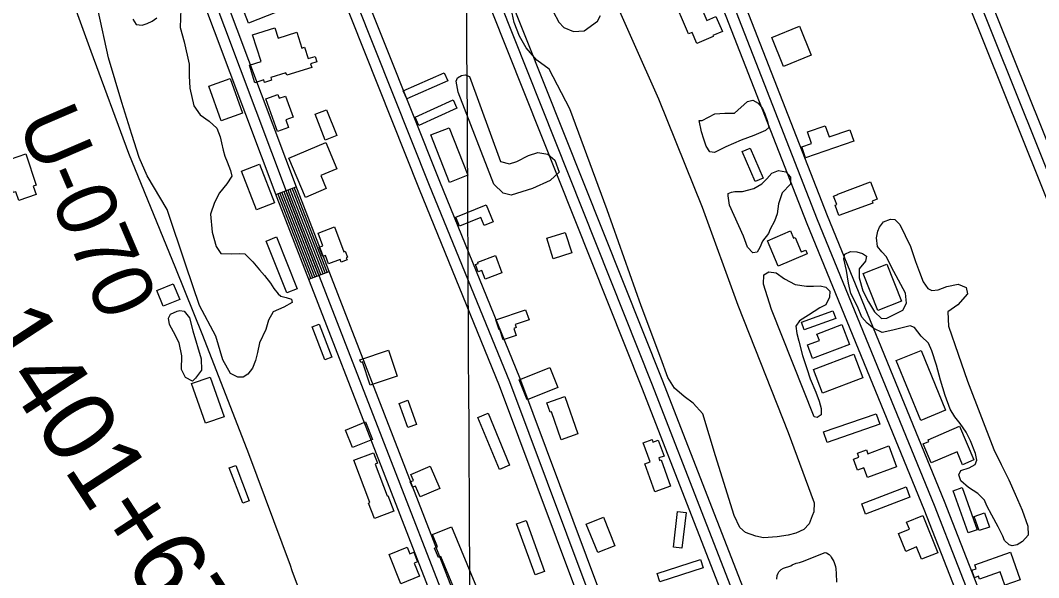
# Model space of a CAD drawing. Extents: x 3445503 to 3483459, y 540493 to 566012.
# Drawn here: x 3475391 to 3476792, y 549267 to 550033 of the extents above; entities that cross this region are included whole.
import ezdxf

# ---------------------------------------------------------------- set-up
doc = ezdxf.new("R2010")
doc.units = 0
for name, color, linetype in [('V-BLDG-OTLN', 7, 'Continuous'), ('V-GRID-MAJR', 7, 'Continuous'), ('V-RIVR-RANG-IDEN', 7, 'Continuous'), ('V-ROAD-CNTR', 7, 'Continuous'), ('V-SITE-VEGE', 7, 'Continuous'), ('V-SURV-IDEN', 7, 'Continuous')]:
    doc.layers.add(name, color=color, linetype=linetype)

msp = doc.modelspace()

# ---------------------------------------------------------------- linework, layer by layer
at = {"layer": 'V-BLDG-OTLN'}
for points in [[(3475743.2, 550044.1), (3475704.4, 550029.3), (3475685.8, 550078), (3475724.6, 550092.8)], [(3476310, 550014.4), (3476287.5, 550067.2), (3476318.5, 550080.4), (3476327.3, 550059.6), (3476324.2, 550058.3), (3476334.9, 550033), (3476347.7, 550038.4), (3476356.5, 550017.9), (3476343.3, 550012.3), (3476344, 550010.7), (3476321.5, 550001.1), (3476314.9, 550016.5)], [(3476462.6, 550024.8), (3476478.8, 549985), (3476440.7, 549969.5), (3476424.5, 550009.3)], [(3475713.4, 549947.3), (3475705.8, 549971.4), (3475721.8, 549976.4), (3475710.2, 550012.9), (3475740.9, 550022.6), (3475745.3, 550008.6), (3475771, 550016.7), (3475777.8, 549995), (3475781.7, 549996.2), (3475786.6, 549980.4), (3475796.5, 549983.5), (3475798.8, 549976), (3475790.1, 549973.3), (3475791.7, 549968.3), (3475757.2, 549957.5), (3475756.1, 549960.9), (3475735.1, 549954.3), (3475736.3, 549950.6), (3475726.6, 549947.5), (3475725.5, 549951.2)], [(3475917.5, 549936.1), (3475973.9, 549960.9), (3475978.8, 549949.7), (3475922.4, 549925)], [(3475666.9, 549894.8), (3475649.9, 549942.4), (3475679.2, 549952.9), (3475696.2, 549905.3)], [(3475744.7, 549880.2), (3475728.5, 549925), (3475745.1, 549931), (3475746.9, 549925.9), (3475755.6, 549929), (3475766.1, 549899.8), (3475755.9, 549896.2), (3475759.7, 549885.6)], [(3475933.7, 549900.1), (3475986, 549923.9), (3475991.3, 549912.2), (3475939.1, 549888.4)], [(3475812.1, 549910.2), (3475826, 549874.6), (3475810.2, 549868.4), (3475796.3, 549904)], [(3475980.7, 549885.3), (3476006.2, 549820.1), (3475981.2, 549810.3), (3475955.6, 549875.4)], [(3476537.3, 549866.9), (3476470.7, 549844.1), (3476465.7, 549858.9), (3476479, 549863.5), (3476473.5, 549879.6), (3476498.1, 549888), (3476503.4, 549872.7), (3476531.9, 549882.4)], [(3475782.9, 549789.6), (3475760, 549843.7), (3475811, 549865.3), (3475826.3, 549829.1), (3475804.1, 549819.6), (3475811.6, 549801.7)], [(3476401.8, 549811.5), (3476383.8, 549852.6), (3476394.7, 549857.3), (3476412.7, 549816.2)], [(3475381, 549796.2), (3475366.7, 549838.7), (3475398.1, 549849.3), (3475412.5, 549806.4), (3475408.4, 549805), (3475412.3, 549793.4), (3475388.6, 549785.4), (3475384.6, 549797.4)], [(3475719.8, 549835.3), (3475740.5, 549782.2), (3475715.8, 549772.6), (3475695.1, 549825.7)], [(3476516.9, 549764.5), (3476511.5, 549778.8), (3476514, 549779.7), (3476509.6, 549791.4), (3476515.3, 549793.5), (3476515.2, 549794), (3476560.4, 549811), (3476569.4, 549787.2), (3476562.4, 549784.5), (3476563.3, 549781.9)], [(3476031.6, 549779.3), (3476041, 549755.8), (3476028.7, 549750.8), (3476024.2, 549762), (3475994.8, 549750.2), (3475989.8, 549762.6)], [(3475800.3, 549740.6), (3475823, 549749.1), (3475835.8, 549715), (3475837.8, 549715.8), (3475841, 549707.5), (3475838.9, 549706.7), (3475840.1, 549703.6), (3475832.1, 549700.5), (3475830.7, 549704.1), (3475814.7, 549698.1), (3475810.4, 549709.6), (3475806.8, 549708.2), (3475801.9, 549721.2), (3475806.9, 549723.1)], [(3475757.3, 549658.4), (3475729, 549729.6), (3475743.2, 549735.2), (3475771.5, 549664)], [(3476123.9, 549705.3), (3476115, 549733.5), (3476140.3, 549741.5), (3476149.2, 549713.3)], [(3476418.5, 549730), (3476450.4, 549743.5), (3476454.5, 549733.7), (3476456.6, 549734.5), (3476465, 549714.6), (3476471.2, 549717.2), (3476473.3, 549712.2), (3476433.2, 549695.2)], [(3476044.2, 549709.7), (3476053.2, 549685.7), (3476030.2, 549677.1), (3476025.8, 549689.1), (3476020.7, 549687.2), (3476016.8, 549697.5), (3476020.5, 549698.9), (3476019.9, 549700.6)], [(3476582.9, 549698), (3476603.1, 549647.1), (3476570.3, 549634.1), (3476550.1, 549684.9)], [(3475601, 549671), (3475609.9, 549649.3), (3475587.3, 549640), (3475578.3, 549661.7)], [(3476044.7, 549621.3), (3476085.8, 549635.2), (3476090.6, 549621.1), (3476071.6, 549614.7), (3476073, 549610.6), (3476069.7, 549609.5), (3476073, 549599.9), (3476055.1, 549593.8), (3476050.4, 549607.8), (3476049.4, 549607.5)], [(3476465.2, 549618), (3476508.6, 549633.6), (3476512.4, 549623.1), (3476468.9, 549607.5)], [(3475809.7, 549566.3), (3475792.3, 549611.5), (3475801.6, 549615.2), (3475819.1, 549569.9)], [(3476486.6, 549601.7), (3476520.8, 549614.7), (3476531.2, 549587.2), (3476480.7, 549568), (3476473.5, 549586.9), (3476489.9, 549593.1)], [(3475857.9, 549566.5), (3475897.2, 549579.4), (3475909, 549543.7), (3475872.1, 549531.6), (3475861.6, 549563.4), (3475859.2, 549562.6)], [(3476629.5, 549483), (3476595.8, 549565.3), (3476629.9, 549579.2), (3476663.5, 549496.9)], [(3476549.5, 549541.6), (3476494.1, 549520.6), (3476481.8, 549553), (3476537.2, 549574.1)], [(3476130.3, 549528.4), (3476087.8, 549511.3), (3476076.8, 549538.6), (3476119.3, 549555.7)], [(3475651.7, 549542.6), (3475670.9, 549488.1), (3475645.6, 549479.2), (3475626.4, 549533.7)], [(3475923.8, 549473.1), (3475911.7, 549506.3), (3475923.8, 549510.7), (3475935.9, 549477.4)], [(3476139.8, 549515.8), (3476157.7, 549464.6), (3476134.6, 549456.5), (3476121.2, 549495), (3476119.4, 549494.4), (3476114.9, 549507.2)], [(3476049.8, 549415.6), (3476020.2, 549487.2), (3476034.1, 549493), (3476063.7, 549421.4)], [(3476495.8, 549467.2), (3476567.9, 549492.2), (3476572.9, 549477.8), (3476500.8, 549452.8)], [(3475875.3, 549457), (3475847.6, 549445.8), (3475837.9, 549469.8), (3475865.6, 549481)], [(3476682.7, 549474.9), (3476702.5, 549428.7), (3476687, 549422), (3476679.3, 549440), (3476643.6, 549424.8), (3476632.6, 549450.6), (3476640.5, 549454), (3476639.4, 549456.4)], [(3476263.5, 549384.9), (3476249.6, 549423.2), (3476257, 549425.9), (3476247.5, 549452.1), (3476259.9, 549456.6), (3476261, 549453.3), (3476268.3, 549455.9), (3476276.2, 549434), (3476268.9, 549431.4), (3476270.1, 549428), (3476272.1, 549428.8), (3476285.1, 549392.7)], [(3475877.8, 549348.1), (3475869.7, 549369.3), (3475871.5, 549370), (3475849.3, 549428.3), (3475876.5, 549438.6), (3475882, 549424.1), (3475878.8, 549422.9), (3475895.4, 549379.3), (3475896.3, 549379.7), (3475904.5, 549358.2)], [(3476596.2, 549419.3), (3476556, 549404.6), (3476551.1, 549417.8), (3476542.5, 549414.7), (3476536.9, 549429.8), (3476544.2, 549432.5), (3476542.2, 549438), (3476554.8, 549442.6), (3476556.8, 549437.2), (3476585.7, 549447.9)], [(3475696.6, 549369.3), (3475678.2, 549417.9), (3475687, 549421.2), (3475705.4, 549372.6)], [(3475954.6, 549420), (3475967.7, 549389.5), (3475940.7, 549378), (3475934.4, 549392.8), (3475930.3, 549391.1), (3475927.2, 549398.4), (3475931.7, 549400.3), (3475928.1, 549408.7)], [(3476548.2, 549368.2), (3476609.2, 549391.5), (3476614.6, 549377.3), (3476553.6, 549354)], [(3476694.6, 549328.5), (3476674, 549386.2), (3476686.2, 549390.6), (3476706.8, 549332.8)], [(3476289.4, 549308.7), (3476294.9, 549357.8), (3476306.5, 549356.5), (3476300.9, 549307.4)], [(3476632.2, 549352.1), (3476652.8, 549301.2), (3476630.5, 549292.1), (3476623.6, 549309), (3476608.9, 549303), (3476599, 549327.4), (3476613.7, 549333.4), (3476609.8, 549343)], [(3476709.8, 549331.5), (3476703.1, 549350.9), (3476717.2, 549355.8), (3476723.9, 549336.4)], [(3476098.9, 549270.6), (3476073.4, 549340.8), (3476086.4, 549345.5), (3476111.9, 549275.3)], [(3476192.9, 549350.1), (3476208.6, 549310.8), (3476185, 549301.3), (3476169.2, 549340.6)], [(3475984, 549336.9), (3476018.1, 549253.6), (3475991.2, 549242.6), (3475969.4, 549295.9), (3475965.8, 549294.4), (3475960.4, 549307.6), (3475964.4, 549309.3), (3475957.5, 549326)], [(3475914.3, 549258.4), (3475898.1, 549298.6), (3475922.9, 549308.6), (3475926.5, 549299.5), (3475931.9, 549301.7), (3475937.1, 549288.7), (3475932.5, 549286.9), (3475939.9, 549268.7)], [(3476752.8, 549301.7), (3476766.3, 549263.8), (3476745.3, 549256.4), (3476738.8, 549274.7), (3476710.4, 549264.7), (3476709, 549268.8), (3476703.2, 549266.8), (3476699.6, 549277.1), (3476705.6, 549279.2), (3476703.8, 549284.4)], [(3476266.9, 549272.5), (3476326.5, 549291.7), (3476330.1, 549280.5), (3476270.5, 549261.3)]]:
    msp.add_lwpolyline(points, close=True, dxfattribs=at)
at = {"layer": 'V-GRID-MAJR'}
msp.add_spline([(3476027.1, 546019.5), (3475994.4, 552078.6), (3475961.8, 558139.5), (3475929.2, 564200.5), (3475929.2, 564202.4)], degree=3, dxfattribs=at)
at = {"layer": 'V-ROAD-CNTR'}
for p, q in [((3475742.2, 549793.7), (3475770.3, 549804.3)), ((3475787.5, 549677), (3475815.5, 549687.9))]:
    msp.add_line(p, q, dxfattribs=at)
for points in [[(3478296.3, 546039.2), (3478195.7, 546296.9), (3478120.9, 546488), (3477825.2, 547231), (3477600.7, 547804.3), (3477368.4, 548418.2), (3477244.1, 548737.9), (3476896.7, 549634.2), (3476496.3, 550631.4), (3476398.8, 550925.5)], [(3477343.6, 548398.8), (3477340.4, 548407.5), (3477216.1, 548727.1), (3476868.8, 549623.2), (3476468.1, 550621), (3476372.9, 550908.5)], [(3476396.2, 550885.7), (3476482.2, 550626.2), (3476882.7, 549628.7), (3477230.1, 548732.5), (3477354.4, 548412.9), (3477586.7, 547798.9), (3477811.3, 547225.5), (3478106.9, 546482.4), (3478181.8, 546291.4), (3478282.2, 546034.2)], [(3476119.7, 550739.7), (3476500.6, 549764.8), (3476661.6, 549372.2), (3476889.8, 548787.9), (3477039.2, 548392.8)], [(3476091.7, 550728.7), (3476472.8, 549753.7), (3476633.8, 549361), (3476861.8, 548777.2), (3477011.1, 548382.2)], [(3476105.7, 550734.2), (3476486.7, 549759.2), (3476647.7, 549366.6), (3476875.8, 548782.5), (3477025.1, 548387.5)], [(3475865.9, 550573.8), (3475950.6, 550349.5), (3476273.1, 549539.7), (3476424.4, 549151), (3476669.7, 548517.3), (3476798.4, 548193.1), (3476918.1, 547887.8)], [(3475837.8, 550563.2), (3475922.6, 550338.7), (3476245.2, 549528.7), (3476396.4, 549140.1), (3476641.7, 548506.4), (3476770.4, 548182.1), (3476890.1, 547876.8)], [(3475851.8, 550568.5), (3475936.6, 550344.1), (3476259.2, 549534.2), (3476410.4, 549145.6), (3476655.7, 548511.8), (3476784.4, 548187.6), (3476904.1, 547882.3)], [(3476433.7, 548569), (3476247.4, 549046), (3476063.9, 549536), (3475953.7, 549805.9), (3475803.4, 550183.6), (3475707.7, 550474.5)], [(3476447.6, 548574.5), (3476261.4, 549051.4), (3476077.9, 549541.5), (3475967.6, 549811.5), (3475817.5, 550188.8), (3475722, 550479.2)], [(3476419.7, 548563.6), (3476233.4, 549040.7), (3476050, 549530.5), (3475939.8, 549800.3), (3475789.3, 550178.5), (3475693.5, 550469.8)], [(3476479.9, 547881), (3476106.4, 548855.9), (3475743.9, 549789.2), (3475528.4, 550362.3)], [(3475542.4, 550367.6), (3475757.9, 549794.6), (3476120.4, 548861.3), (3476493.9, 547886.3)], [(3476490, 547938.4), (3476134.4, 548866.7), (3475771.9, 549799.9), (3475556.5, 550372.8)], [(3475375.3, 550248.8), (3475398.5, 550214.6), (3475416.8, 550181.9), (3475441.8, 550117.2), (3475487.6, 549990.8), (3475539.4, 549850.4), (3475604.3, 549692.5), (3475641.4, 549600.1), (3475704.8, 549437.4), (3475762.1, 549283.8), (3475764.1, 549276.9), (3475808.5, 549158), (3475847.7, 549062.8), (3475902.9, 548909.9)], [(3475807.1, 549684.6), (3475763.5, 549796.7), (3475761.9, 549801.1)], [(3475809.9, 549685.7), (3475766.3, 549797.8), (3475764.7, 549802.2)], [(3475812.7, 549686.8), (3475769.1, 549798.8), (3475767.5, 549803.2)], [(3475790.3, 549678.1), (3475746.7, 549790.3), (3475745, 549794.8)], [(3475793.1, 549679.2), (3475749.5, 549791.3), (3475747.8, 549795.8)], [(3475795.9, 549680.3), (3475752.3, 549792.4), (3475750.6, 549796.9)], [(3475798.7, 549681.4), (3475755.1, 549793.5), (3475753.5, 549797.9)], [(3475801.5, 549682.5), (3475757.9, 549794.6), (3475756.3, 549799)], [(3475804.3, 549683.6), (3475760.7, 549795.6), (3475759.1, 549800.1)]]:
    msp.add_lwpolyline(points, dxfattribs=at)
at = {"layer": 'V-SITE-VEGE'}
for points in [[(3476197.9, 550084.1), (3476268.7, 549924.9), (3476328.7, 549776.4), (3476377.9, 549641.5), (3476447.1, 549466.4), (3476483, 549369.8), (3476482.4, 549357.3), (3476480.1, 549351.8), (3476475.8, 549341), (3476468.6, 549333), (3476457.4, 549328.1), (3476447, 549325.4), (3476432, 549322.8), (3476413.3, 549321.8), (3476402.5, 549323.8), (3476388.5, 549328.8), (3476380.7, 549335.6), (3476372.6, 549352.5), (3476346.9, 549434.4), (3476329.7, 549492), (3476316.3, 549506.7), (3476303.9, 549516), (3476290.6, 549527.5), (3476281.3, 549542.1), (3476271.7, 549568.5), (3476245, 549640.5), (3476197.9, 549772.7), (3476146.5, 549911.4), (3476118.2, 549965.9), (3476101.3, 549978.3), (3476086.5, 549995.3), (3476077.6, 550011.1), (3476070.2, 550030.1), (3476067.1, 550042.8)], [(3475611.3, 550049), (3475610.6, 550023.2), (3475616.3, 550003.7), (3475622.9, 549973), (3475623, 549956.9), (3475624, 549939.9), (3475629.5, 549915.4), (3475638.3, 549903.1), (3475650.7, 549894.2), (3475660.9, 549884.7), (3475665.4, 549873.1), (3475667.4, 549864.8), (3475669.6, 549854.7), (3475671.8, 549846.1), (3475675.2, 549838.5), (3475679.9, 549826.7), (3475681.7, 549818.9), (3475674.6, 549808.1), (3475664.6, 549795.8), (3475657.6, 549782.7), (3475652.1, 549766.4), (3475654.4, 549742), (3475660.2, 549721.9), (3475666.5, 549712.7), (3475680.6, 549712), (3475692.8, 549712.6), (3475699.4, 549711.9), (3475710.4, 549700.9), (3475719.7, 549690), (3475726.8, 549682.3), (3475734.7, 549671.7), (3475739.5, 549664.2), (3475745.4, 549657), (3475749, 549653.8), (3475756.6, 549652.1), (3475763.7, 549649.5), (3475764.8, 549645.1), (3475753, 549638.8), (3475738.7, 549632.5), (3475732.3, 549620.8), (3475728.5, 549607.9), (3475719.8, 549589.6), (3475716.9, 549576.3), (3475714.3, 549565.3), (3475710.2, 549554.9), (3475703.7, 549546.7), (3475697.2, 549542.6), (3475689.9, 549542.5), (3475679.6, 549547.5), (3475669.5, 549566.3), (3475659.5, 549598.8), (3475637.1, 549641.2), (3475618.3, 549696.6), (3475592.9, 549772.8), (3475565.1, 549819.4), (3475554.3, 549844.3), (3475544.2, 549876.2), (3475530.2, 549919.9), (3475512.2, 549981.5), (3475497.7, 550046.6)], [(3476123.7, 550045.4), (3476131.4, 550030.4), (3476138.2, 550023.1), (3476151.8, 550017.9), (3476166.5, 550018.5), (3476184.9, 550031.9), (3476188.9, 550039.7)], [(3475545.3, 550034.5), (3475550.1, 550027.5), (3475558.4, 550026.3), (3475565.3, 550028.5), (3475572, 550031.9), (3475578.5, 550036.7)], [(3476431.2, 549264.7), (3476431.9, 549270), (3476433.2, 549272.9), (3476434.3, 549274.8), (3476437.3, 549277.9), (3476440.7, 549280), (3476443.4, 549281), (3476448, 549282), (3476450.6, 549283.3), (3476452.7, 549284.5), (3476458.2, 549286.8), (3476462.4, 549287.8), (3476466.7, 549289), (3476497.7, 549301.5), (3476499.9, 549300.9), (3476503.2, 549298.7), (3476505.1, 549297), (3476506.1, 549295.1), (3476509.8, 549289), (3476511.9, 549282.2), (3476512.5, 549279), (3476513, 549272.7), (3476513.3, 549260.5)]]:
    msp.add_lwpolyline(points, dxfattribs=at)
for points in [[(3476008.6, 549956), (3476051.4, 549838.8), (3476063.6, 549835.7), (3476073.8, 549839), (3476089.6, 549847), (3476102.8, 549851.2), (3476116.3, 549849), (3476125.9, 549840.6), (3476131.8, 549824.1), (3476119.4, 549812.7), (3476095.3, 549801.9), (3476065.9, 549792.5), (3476054.9, 549795.6), (3476042.1, 549807.8), (3475992.9, 549934.5), (3475990.1, 549949.2), (3475991.9, 549953.8), (3475997.5, 549957), (3476002.6, 549957.9)], [(3476328.7, 549895.2), (3476346.3, 549904.7), (3476359.9, 549905.3), (3476373.1, 549905.4), (3476391, 549921.3), (3476398.4, 549923.3), (3476405.7, 549919.1), (3476411.7, 549911.9), (3476415, 549904.5), (3476418.6, 549893.8), (3476420.6, 549885.5), (3476415.7, 549881.4), (3476400, 549874.9), (3476382.4, 549868.2), (3476361.1, 549858.9), (3476345.8, 549851.5), (3476339.3, 549852.2), (3476334.3, 549860.1), (3476331, 549869.6), (3476327.8, 549879.8), (3476324.5, 549895.5)], [(3476373.8, 549797.9), (3476384.2, 549797.8), (3476399.7, 549802), (3476410.8, 549808.1), (3476417.6, 549815), (3476424.6, 549822.8), (3476433.6, 549826.4), (3476444, 549824.6), (3476450.1, 549817.6), (3476450, 549807.7), (3476438.8, 549795.9), (3476433.8, 549780.9), (3476432.1, 549766.9), (3476428, 549756.8), (3476422.2, 549745.8), (3476419.8, 549740), (3476411.6, 549729.5), (3476408.1, 549720.8), (3476404.3, 549714.1), (3476398.5, 549713.5), (3476391, 549721.2), (3476385.4, 549736.2), (3476366.2, 549779.1), (3476364.3, 549791.8), (3476364.3, 549795), (3476369.2, 549796.8)], [(3476600.5, 549752.2), (3476615.2, 549721.9), (3476622.1, 549701.3), (3476627.5, 549686.9), (3476632.9, 549673.7), (3476639.3, 549664.4), (3476644.8, 549661.8), (3476653.5, 549662.7), (3476665.3, 549667.1), (3476680.8, 549670.2), (3476692.1, 549665.9), (3476693.6, 549656.9), (3476680.5, 549641.8), (3476666.6, 549632.1), (3476667.8, 549612.5), (3476681, 549574.3), (3476693.5, 549537.2), (3476729.9, 549443), (3476739.9, 549422.4), (3476750.5, 549401.3), (3476759.5, 549381.4), (3476768.7, 549359.6), (3476776.6, 549337.8), (3476777.1, 549325.1), (3476769.2, 549316.7), (3476762.2, 549311.9), (3476755.1, 549310.8), (3476751.2, 549311.8), (3476744.8, 549317.9), (3476742.5, 549323.9), (3476736, 549336.6), (3476727.1, 549352.9), (3476720.4, 549365.8), (3476717, 549373.5), (3476708.1, 549382.6), (3476695.2, 549390.8), (3476684.7, 549399.9), (3476681.8, 549408.4), (3476684.4, 549414), (3476695.8, 549418), (3476704.1, 549422.3), (3476706.7, 549428.3), (3476704.5, 549437.7), (3476698, 549455.1), (3476691.9, 549466.7), (3476683.5, 549479), (3476676.2, 549488.1), (3476669.8, 549498.7), (3476663.1, 549517.3), (3476656.6, 549538.5), (3476650.9, 549559.1), (3476644.8, 549578.6), (3476640.1, 549589.2), (3476630.1, 549598.8), (3476620.7, 549610.6), (3476615, 549613), (3476591.2, 549607), (3476576.1, 549603.9), (3476564.9, 549609.4), (3476555.5, 549616.8), (3476548.5, 549625), (3476542.4, 549639.4), (3476533.1, 549657.4), (3476529.8, 549671.8), (3476527.4, 549689.1), (3476523.5, 549705.3), (3476525.1, 549711.5), (3476532.8, 549715.1), (3476541.3, 549714.8), (3476549.1, 549712.4), (3476554.6, 549708.6), (3476553.6, 549702), (3476544.5, 549691.4), (3476544.6, 549679.2), (3476549.7, 549661), (3476557.7, 549645.9), (3476565.8, 549632.2), (3476575.4, 549623.3), (3476582.6, 549623.5), (3476604.8, 549634.8), (3476609.8, 549644), (3476608.3, 549657.8), (3476589.1, 549693.8), (3476582.5, 549707.7), (3476575.7, 549714.7), (3476570, 549721.9), (3476568.5, 549734.1), (3476570.4, 549743.1), (3476572.6, 549748.6), (3476578.2, 549755.9), (3476587.9, 549759.7), (3476593.9, 549759)], [(3476482.9, 549487.8), (3476424, 549635.7), (3476413.3, 549670.2), (3476413.5, 549683.1), (3476420.2, 549687.4), (3476430.5, 549685.7), (3476442, 549677.7), (3476456.7, 549669.8), (3476472.1, 549667.8), (3476481.8, 549667.4), (3476491, 549668.2), (3476498.8, 549666.3), (3476504.3, 549660.7), (3476504, 549652.4), (3476499, 549642.1), (3476490.7, 549637.6), (3476475.1, 549627.8), (3476462.6, 549620.1), (3476457.5, 549612.6), (3476459, 549602.4), (3476461.9, 549591.8), (3476466.7, 549572.1), (3476472.8, 549554.3), (3476477.2, 549540.2), (3476485.1, 549521.9), (3476489.6, 549509.6), (3476492.5, 549499.4), (3476492.4, 549490.9), (3476486.8, 549486.8)], [(3475609.9, 549633.9), (3475616.1, 549633.1), (3475623.6, 549624), (3475628.2, 549606), (3475639.6, 549567.9), (3475640.1, 549552.1), (3475631.7, 549541.1), (3475627.5, 549537), (3475617.9, 549541.9), (3475612.5, 549553), (3475612.7, 549571.7), (3475609.4, 549589.7), (3475601.3, 549604.9), (3475595.9, 549614.7), (3475594.6, 549623.7), (3475597.4, 549629.1), (3475606.4, 549633.2)]]:
    msp.add_lwpolyline(points, close=True, dxfattribs=at)

# ---------------------------------------------------------------- texts
at = {"layer": 'V-RIVR-RANG-IDEN'}
msp.add_text('U-070', height=83, rotation=293.2183, dxfattribs=at).set_placement((3475385.8, 549893.8))
at = {"layer": 'V-SURV-IDEN'}
msp.add_text('1401+67.2', height=100, rotation=303.1347, dxfattribs=at).set_placement((3475327.5, 549602.7))

doc.saveas('drawing.dxf')
